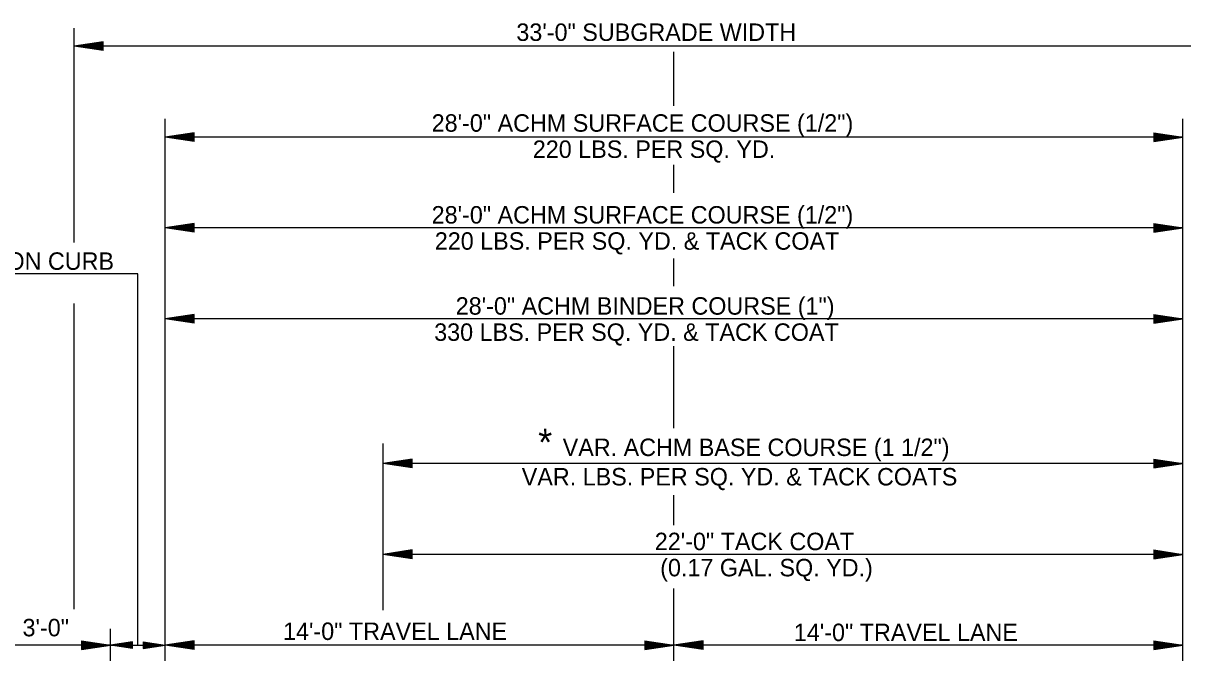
# Model space of a CAD drawing. Extents: x 635488 to 635865, y 290537 to 290973.
# Drawn here: x 635679.67 to 635719.55, y 290678.18 to 290699.83 of the extents above; entities that cross this region are included whole.
import ezdxf

# ---------------------------------------------------------------- set-up
doc = ezdxf.new("R2010")
doc.units = 0
for name, color, linetype in [('Level 13', 7, 'Continuous'), ('Level 43', 7, 'Continuous'), ('R_Border', 7, 'Continuous'), ('R_Dimension', 7, 'Continuous')]:
    doc.layers.add(name, color=color, linetype=linetype)

msp = doc.modelspace()

# ---------------------------------------------------------------- linework, layer by layer
at = {"layer": 'Level 43'}
for p, q in [((635681.426, 290692.285), (635681.426, 290699.661)), ((635722.676, 290699.036), (635681.426, 290699.036)), ((635684.551, 290670.5), (635684.551, 290696.536)), ((635719.551, 290670.5), (635719.551, 290696.536)), ((635719.551, 290695.911), (635684.551, 290695.911)), ((635719.551, 290692.786), (635684.551, 290692.786)), ((635683.613, 290691.21), (635669.68, 290691.21)), ((635683.613, 290678.439), (635683.613, 290691.21)), ((635681.426, 290679.685), (635681.426, 290690.185)), ((635719.551, 290689.661), (635684.551, 290689.661)), ((635692.051, 290679.641), (635692.051, 290685.379)), ((635719.551, 290684.689), (635692.051, 290684.689)), ((635719.551, 290681.564), (635692.051, 290681.564)), ((635682.675, 290670.5), (635682.675, 290678.999)), ((635682.675, 290678.438), (635678.425, 290678.438)), ((635682.675, 290678.438), (635678.425, 290678.438)), ((635682.675, 290678.439), (635684.55, 290678.439)), ((635702.051, 290678.439), (635684.55, 290678.439)), ((635719.551, 290678.439), (635702.051, 290678.439))]:
    msp.add_line(p, q, dxfattribs=at)
at = {"layer": 'R_Border'}
for p, q in [((635702.051, 290696.988), (635702.051, 290698.842)), ((635702.051, 290693.997), (635702.051, 290694.961)), ((635702.051, 290690.786), (635702.051, 290691.736)), ((635702.051, 290685.897), (635702.051, 290688.727)), ((635702.051, 290682.564), (635702.051, 290683.6)), ((635702.051, 290669.7), (635702.051, 290680.388))]:
    msp.add_line(p, q, dxfattribs=at)
at = {"layer": 'R_Dimension'}
for p, q in [((635682.426, 290699.186), (635681.426, 290699.036)), ((635682.426, 290699.161), (635681.593, 290699.036)), ((635682.426, 290699.135), (635681.765, 290699.036)), ((635682.426, 290699.11), (635681.931, 290699.036)), ((635682.426, 290699.085), (635682.101, 290699.036)), ((635682.426, 290698.886), (635682.426, 290699.186)), ((635682.426, 290698.886), (635681.426, 290699.036)), ((635682.426, 290698.911), (635681.593, 290699.036)), ((635682.426, 290698.936), (635681.765, 290699.036)), ((635682.426, 290698.961), (635681.931, 290699.036)), ((635682.426, 290698.987), (635682.101, 290699.036)), ((635682.426, 290699.059), (635682.268, 290699.036)), ((635682.426, 290699.012), (635682.268, 290699.036)), ((635685.551, 290696.061), (635684.551, 290695.911)), ((635685.551, 290695.761), (635684.551, 290695.911)), ((635685.551, 290696.036), (635684.718, 290695.911)), ((635685.551, 290695.786), (635684.718, 290695.911)), ((635685.551, 290696.01), (635684.89, 290695.911)), ((635685.551, 290695.811), (635684.89, 290695.911)), ((635685.551, 290695.985), (635685.056, 290695.911)), ((635685.551, 290695.836), (635685.056, 290695.911)), ((635685.551, 290695.96), (635685.226, 290695.911)), ((635685.551, 290695.862), (635685.226, 290695.911)), ((635685.551, 290695.934), (635685.393, 290695.911)), ((635685.551, 290695.887), (635685.393, 290695.911)), ((635685.551, 290695.761), (635685.551, 290696.061)), ((635718.551, 290696.061), (635719.551, 290695.911)), ((635718.551, 290696.061), (635718.551, 290695.761)), ((635718.551, 290696.036), (635719.384, 290695.911)), ((635718.551, 290696.01), (635719.212, 290695.911)), ((635718.551, 290695.985), (635719.045, 290695.911)), ((635718.551, 290695.959), (635718.876, 290695.911)), ((635718.551, 290695.934), (635718.709, 290695.911)), ((635718.551, 290695.761), (635719.551, 290695.911)), ((635718.551, 290695.862), (635718.876, 290695.911)), ((635718.551, 290695.811), (635719.212, 290695.911)), ((635718.551, 290695.786), (635719.384, 290695.911)), ((635718.551, 290695.836), (635719.045, 290695.911)), ((635718.551, 290695.887), (635718.709, 290695.911)), ((635685.551, 290692.936), (635684.551, 290692.786)), ((635685.551, 290692.636), (635684.551, 290692.786)), ((635685.551, 290692.911), (635684.718, 290692.786)), ((635685.551, 290692.661), (635684.718, 290692.786)), ((635685.551, 290692.885), (635684.89, 290692.786)), ((635685.551, 290692.686), (635684.89, 290692.786)), ((635685.551, 290692.86), (635685.056, 290692.786)), ((635685.551, 290692.711), (635685.056, 290692.786)), ((635685.551, 290692.835), (635685.226, 290692.786)), ((635685.551, 290692.737), (635685.226, 290692.786)), ((635685.551, 290692.809), (635685.393, 290692.786)), ((635685.551, 290692.762), (635685.393, 290692.786)), ((635685.551, 290692.636), (635685.551, 290692.936)), ((635718.551, 290692.936), (635719.551, 290692.786)), ((635718.551, 290692.936), (635718.551, 290692.636)), ((635718.551, 290692.911), (635719.384, 290692.786)), ((635718.551, 290692.885), (635719.212, 290692.786)), ((635718.551, 290692.86), (635719.045, 290692.786)), ((635718.551, 290692.834), (635718.876, 290692.786)), ((635718.551, 290692.809), (635718.709, 290692.786)), ((635718.551, 290692.636), (635719.551, 290692.786)), ((635718.551, 290692.737), (635718.876, 290692.786)), ((635718.551, 290692.686), (635719.212, 290692.786)), ((635718.551, 290692.661), (635719.384, 290692.786)), ((635718.551, 290692.711), (635719.045, 290692.786)), ((635718.551, 290692.762), (635718.709, 290692.786)), ((635685.551, 290689.811), (635684.551, 290689.661)), ((635685.551, 290689.511), (635684.551, 290689.661)), ((635685.551, 290689.786), (635684.718, 290689.661)), ((635685.551, 290689.536), (635684.718, 290689.661)), ((635685.551, 290689.76), (635684.89, 290689.661)), ((635685.551, 290689.561), (635684.89, 290689.661)), ((635685.551, 290689.735), (635685.056, 290689.661)), ((635685.551, 290689.586), (635685.056, 290689.661)), ((635685.551, 290689.71), (635685.226, 290689.661)), ((635685.551, 290689.612), (635685.226, 290689.661)), ((635685.551, 290689.684), (635685.393, 290689.661)), ((635685.551, 290689.637), (635685.393, 290689.661)), ((635685.551, 290689.511), (635685.551, 290689.811)), ((635718.551, 290689.811), (635719.551, 290689.661)), ((635718.551, 290689.811), (635718.551, 290689.511)), ((635718.551, 290689.786), (635719.384, 290689.661)), ((635718.551, 290689.76), (635719.212, 290689.661)), ((635718.551, 290689.735), (635719.045, 290689.661)), ((635718.551, 290689.709), (635718.876, 290689.661)), ((635718.551, 290689.684), (635718.709, 290689.661)), ((635718.551, 290689.511), (635719.551, 290689.661)), ((635718.551, 290689.612), (635718.876, 290689.661)), ((635718.551, 290689.561), (635719.212, 290689.661)), ((635718.551, 290689.536), (635719.384, 290689.661)), ((635718.551, 290689.586), (635719.045, 290689.661)), ((635718.551, 290689.637), (635718.709, 290689.661)), ((635693.051, 290684.839), (635692.051, 290684.689)), ((635693.051, 290684.814), (635692.218, 290684.689)), ((635693.051, 290684.788), (635692.39, 290684.689)), ((635693.051, 290684.763), (635692.556, 290684.689)), ((635693.051, 290684.738), (635692.726, 290684.689)), ((635693.051, 290684.712), (635692.893, 290684.689)), ((635693.051, 290684.539), (635693.051, 290684.839)), ((635718.551, 290684.839), (635719.551, 290684.689)), ((635718.551, 290684.839), (635718.551, 290684.539)), ((635718.551, 290684.814), (635719.384, 290684.689)), ((635718.551, 290684.788), (635719.212, 290684.689)), ((635718.551, 290684.763), (635719.045, 290684.689)), ((635718.551, 290684.737), (635718.876, 290684.689)), ((635718.551, 290684.712), (635718.709, 290684.689)), ((635693.051, 290684.539), (635692.051, 290684.689)), ((635693.051, 290684.564), (635692.218, 290684.689)), ((635693.051, 290684.589), (635692.39, 290684.689)), ((635693.051, 290684.614), (635692.556, 290684.689)), ((635693.051, 290684.64), (635692.726, 290684.689)), ((635693.051, 290684.665), (635692.893, 290684.689)), ((635718.551, 290684.539), (635719.551, 290684.689)), ((635718.551, 290684.64), (635718.876, 290684.689)), ((635718.551, 290684.589), (635719.212, 290684.689)), ((635718.551, 290684.564), (635719.384, 290684.689)), ((635718.551, 290684.614), (635719.045, 290684.689)), ((635718.551, 290684.665), (635718.709, 290684.689)), ((635693.051, 290681.714), (635692.051, 290681.564)), ((635693.051, 290681.414), (635692.051, 290681.564)), ((635693.051, 290681.689), (635692.218, 290681.564)), ((635693.051, 290681.439), (635692.218, 290681.564)), ((635693.051, 290681.663), (635692.39, 290681.564)), ((635693.051, 290681.464), (635692.39, 290681.564)), ((635693.051, 290681.638), (635692.556, 290681.564)), ((635693.051, 290681.489), (635692.556, 290681.564)), ((635693.051, 290681.613), (635692.726, 290681.564)), ((635693.051, 290681.515), (635692.726, 290681.564)), ((635693.051, 290681.587), (635692.893, 290681.564)), ((635693.051, 290681.54), (635692.893, 290681.564)), ((635693.051, 290681.414), (635693.051, 290681.714)), ((635718.551, 290681.714), (635719.551, 290681.564)), ((635718.551, 290681.714), (635718.551, 290681.414)), ((635718.551, 290681.689), (635719.384, 290681.564)), ((635718.551, 290681.663), (635719.212, 290681.564)), ((635718.551, 290681.638), (635719.045, 290681.564)), ((635718.551, 290681.612), (635718.876, 290681.564)), ((635718.551, 290681.587), (635718.709, 290681.564)), ((635718.551, 290681.414), (635719.551, 290681.564)), ((635718.551, 290681.515), (635718.876, 290681.564)), ((635718.551, 290681.464), (635719.212, 290681.564)), ((635718.551, 290681.439), (635719.384, 290681.564)), ((635718.551, 290681.489), (635719.045, 290681.564)), ((635718.551, 290681.54), (635718.709, 290681.564)), ((635681.675, 290678.588), (635682.675, 290678.438)), ((635681.675, 290678.588), (635681.675, 290678.288)), ((635681.675, 290678.588), (635682.675, 290678.438)), ((635681.675, 290678.588), (635681.675, 290678.288)), ((635681.675, 290678.563), (635682.508, 290678.438)), ((635681.675, 290678.563), (635682.508, 290678.438)), ((635681.675, 290678.538), (635682.336, 290678.438)), ((635681.675, 290678.538), (635682.336, 290678.438)), ((635681.675, 290678.513), (635682.169, 290678.438)), ((635681.675, 290678.513), (635682.169, 290678.438)), ((635681.675, 290678.487), (635682, 290678.438)), ((635681.675, 290678.487), (635682, 290678.438)), ((635681.675, 290678.462), (635681.833, 290678.438)), ((635681.675, 290678.462), (635681.833, 290678.438)), ((635681.675, 290678.288), (635682.675, 290678.438)), ((635681.675, 290678.389), (635682, 290678.438)), ((635681.675, 290678.339), (635682.336, 290678.438)), ((635681.675, 290678.313), (635682.508, 290678.438)), ((635681.675, 290678.364), (635682.169, 290678.438)), ((635681.675, 290678.415), (635681.833, 290678.438)), ((635681.675, 290678.288), (635682.675, 290678.438)), ((635681.675, 290678.389), (635682, 290678.438)), ((635681.675, 290678.339), (635682.336, 290678.438)), ((635681.675, 290678.313), (635682.508, 290678.438)), ((635681.675, 290678.364), (635682.169, 290678.438)), ((635681.675, 290678.415), (635681.833, 290678.438)), ((635683.425, 290678.551), (635682.675, 290678.439)), ((635683.425, 290678.326), (635682.675, 290678.439)), ((635683.425, 290678.533), (635682.801, 290678.439)), ((635683.425, 290678.345), (635682.801, 290678.439)), ((635683.425, 290678.513), (635682.93, 290678.439)), ((635683.425, 290678.364), (635682.93, 290678.439)), ((635683.425, 290678.495), (635683.055, 290678.439)), ((635683.425, 290678.383), (635683.055, 290678.439)), ((635683.425, 290678.476), (635683.182, 290678.439)), ((635683.425, 290678.402), (635683.182, 290678.439)), ((635683.425, 290678.456), (635683.307, 290678.439)), ((635683.425, 290678.421), (635683.307, 290678.439)), ((635683.425, 290678.326), (635683.425, 290678.551)), ((635683.8, 290678.551), (635684.55, 290678.439)), ((635683.8, 290678.551), (635683.8, 290678.326)), ((635683.8, 290678.533), (635684.425, 290678.439)), ((635683.8, 290678.513), (635684.296, 290678.439)), ((635683.8, 290678.495), (635684.171, 290678.439)), ((635683.8, 290678.475), (635684.044, 290678.439)), ((635683.8, 290678.456), (635683.919, 290678.439)), ((635683.8, 290678.326), (635684.55, 290678.439)), ((635683.8, 290678.402), (635684.044, 290678.439)), ((635683.8, 290678.364), (635684.296, 290678.439)), ((635683.8, 290678.345), (635684.425, 290678.439)), ((635683.8, 290678.383), (635684.171, 290678.439)), ((635683.8, 290678.421), (635683.919, 290678.439)), ((635685.55, 290678.589), (635684.55, 290678.439)), ((635685.55, 290678.289), (635684.55, 290678.439)), ((635685.55, 290678.564), (635684.717, 290678.439)), ((635685.55, 290678.314), (635684.717, 290678.439)), ((635685.55, 290678.538), (635684.889, 290678.439)), ((635685.55, 290678.339), (635684.889, 290678.439)), ((635685.55, 290678.513), (635685.056, 290678.439)), ((635685.55, 290678.364), (635685.056, 290678.439)), ((635685.55, 290678.488), (635685.225, 290678.439)), ((635685.55, 290678.39), (635685.225, 290678.439)), ((635685.55, 290678.462), (635685.392, 290678.439)), ((635685.55, 290678.415), (635685.392, 290678.439)), ((635685.55, 290678.289), (635685.55, 290678.589)), ((635701.051, 290678.589), (635702.051, 290678.439)), ((635701.051, 290678.589), (635701.051, 290678.289)), ((635701.051, 290678.564), (635701.884, 290678.439)), ((635701.051, 290678.538), (635701.712, 290678.439)), ((635701.051, 290678.513), (635701.545, 290678.439)), ((635701.051, 290678.487), (635701.376, 290678.439)), ((635701.051, 290678.462), (635701.209, 290678.439)), ((635701.051, 290678.289), (635702.051, 290678.439)), ((635701.051, 290678.39), (635701.376, 290678.439)), ((635701.051, 290678.339), (635701.712, 290678.439)), ((635701.051, 290678.314), (635701.884, 290678.439)), ((635701.051, 290678.364), (635701.545, 290678.439)), ((635701.051, 290678.415), (635701.209, 290678.439)), ((635703.051, 290678.589), (635702.051, 290678.439)), ((635703.051, 290678.289), (635702.051, 290678.439)), ((635703.051, 290678.564), (635702.218, 290678.439)), ((635703.051, 290678.314), (635702.218, 290678.439)), ((635703.051, 290678.538), (635702.39, 290678.439)), ((635703.051, 290678.339), (635702.39, 290678.439)), ((635703.051, 290678.513), (635702.556, 290678.439)), ((635703.051, 290678.364), (635702.556, 290678.439)), ((635703.051, 290678.488), (635702.726, 290678.439)), ((635703.051, 290678.39), (635702.726, 290678.439)), ((635703.051, 290678.462), (635702.893, 290678.439)), ((635703.051, 290678.415), (635702.893, 290678.439)), ((635703.051, 290678.289), (635703.051, 290678.589)), ((635718.551, 290678.589), (635719.551, 290678.439)), ((635718.551, 290678.589), (635718.551, 290678.289)), ((635718.551, 290678.564), (635719.384, 290678.439)), ((635718.551, 290678.538), (635719.212, 290678.439)), ((635718.551, 290678.513), (635719.045, 290678.439)), ((635718.551, 290678.487), (635718.876, 290678.439)), ((635718.551, 290678.462), (635718.709, 290678.439)), ((635718.551, 290678.289), (635719.551, 290678.439)), ((635718.551, 290678.39), (635718.876, 290678.439)), ((635718.551, 290678.339), (635719.212, 290678.439)), ((635718.551, 290678.314), (635719.384, 290678.439)), ((635718.551, 290678.364), (635719.045, 290678.439)), ((635718.551, 290678.415), (635718.709, 290678.439))]:
    msp.add_line(p, q, dxfattribs=at)

# ---------------------------------------------------------------- texts
at = {"layer": 'Level 13'}
for s, height, p in [('33\'-0" SUBGRADE WIDTH', 0.6, (635696.632, 290699.217)), ('28\'-0" ACHM SURFACE COURSE (1/2")', 0.6, (635693.719, 290696.095)), ('220 LBS. PER SQ. YD.', 0.6, (635697.197, 290695.195)), ('28\'-0" ACHM SURFACE COURSE (1/2")', 0.6, (635693.719, 290692.938)), ('220 LBS. PER SQ. YD. & TACK COAT', 0.6, (635693.826, 290692.038)), ('CONCRETE COMBINATION CURB', 0.6, (635669.913, 290691.347)), ('28\'-0" ACHM BINDER COURSE (1")', 0.6, (635694.546, 290689.805)), ('330 LBS. PER SQ. YD. & TACK COAT', 0.6, (635693.806, 290688.905)), ('*', 0.931, (635697.382, 290684.953)), ('VAR. ACHM BASE COURSE (1 1/2")', 0.6, (635698.225, 290684.944)), ('VAR. LBS. PER SQ. YD. & TACK COATS', 0.6, (635696.817, 290683.933)), ('22\'-0" TACK COAT', 0.6, (635701.392, 290681.708)), ('(0.17 GAL. SQ. YD.)', 0.6, (635701.578, 290680.808)), ('3\'-0"', 0.6, (635679.649, 290678.746)), ('14\'-0" TRAVEL LANE', 0.6, (635688.607, 290678.62)), ('14\'-0" TRAVEL LANE', 0.6, (635706.174, 290678.582))]:
    msp.add_text(s, height=height, dxfattribs=at).set_placement(p)

doc.saveas('drawing.dxf')
